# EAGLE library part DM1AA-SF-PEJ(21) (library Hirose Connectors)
CONNECTOR, SD MEMORY CARD SOCKET, SMD (HIROSE)
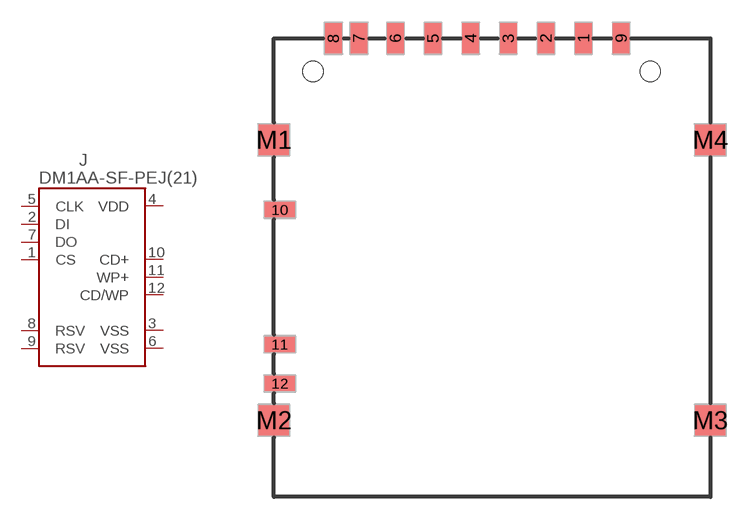
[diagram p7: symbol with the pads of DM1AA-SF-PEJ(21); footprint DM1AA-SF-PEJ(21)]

Designator prefix J

## DM1AA-SF-PEJ(21)  [DM1AA-SF-PEJ(21)]
1  CS
2  DI
3  VSS
4  VDD
5  CLK
6  VSS
7  DO
8  RSV
9  RSV
10  CD+
11  WP+
12  CD/WP

## Footprint DM1AA-SF-PEJ(21) (pad centres in mm)
smd 1.1 x 2: 1 17.975,2.2; 2 15.475,2.2; 3 12.975,2.2; 4 10.475,2.2; 5 7.975,2.2; 6 5.475,2.2; 7 3.05,2.2; 8 1.35,2.2; 9 20.475,2.2
smd 2 x 1: 10 -2.2,-9.2; 11 -2.2,-18.15; 12 -2.2,-20.75
smd 2 x 2: M1 -2.6,-4.55; M2 -2.6,-23.2; M3 26.4,-23.2; M4 26.4,-4.55
hole 1.346 at 0,0
hole 1.346 at 22.4,0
